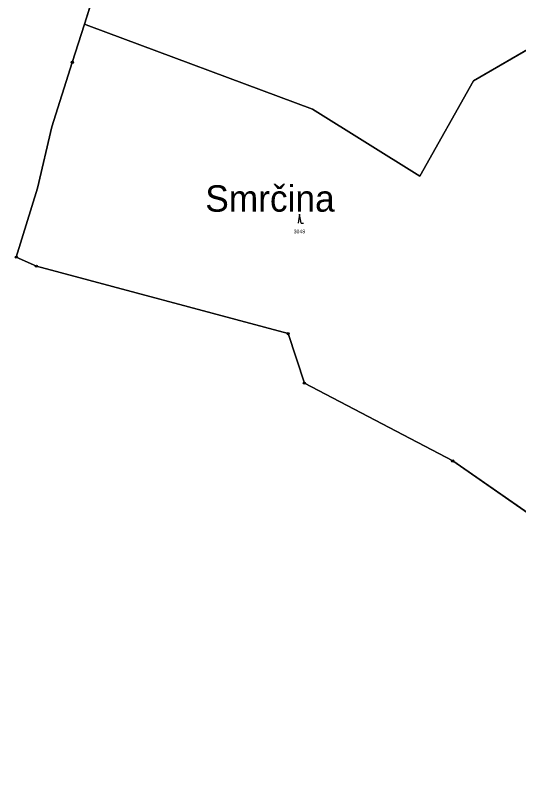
# Model space of a CAD drawing. Extents: x -689422 to -685210, y -987725 to -982160.
# Drawn here: x -688746.1 to -688517.1, y -986803.6 to -986459.2 of the extents above; entities that cross this region are included whole.
import ezdxf

# ---------------------------------------------------------------- set-up
doc = ezdxf.new("R2010")
doc.units = 0
for name, color, linetype in [('KN_Hranice obce', 7, 'Continuous'), ('KN_Hranice_katastrální území', 7, 'Continuous'), ('KN_Hranice_parcel', 7, 'Continuous'), ('KN_Parcelni cisla', 7, 'Continuous'), ('KN_Polygon parcely', 7, 'Continuous'), ('KN_Popisy_pomistni nazvy', 7, 'Continuous'), ('KN_POZEMKY_LESNI POZEMEK', 7, 'Continuous'), ('KN_POZEMKY_TTP', 7, 'Continuous'), ('KN_Značky bodu BP', 7, 'Continuous'), ('KN_Značky kultur', 7, 'Continuous')]:
    doc.layers.add(name, color=color, linetype=linetype)

msp = doc.modelspace()

# ---------------------------------------------------------------- linework, layer by layer
at = {"layer": 'KN_Hranice obce'}
msp.add_lwpolyline([(-688702.54, -986425.02), (-688714.66, -986463.31), (-688720.16, -986480.67), (-688729.49, -986509.98), (-688735.94, -986537.91), (-688745.64, -986569.21), (-688736.48, -986573.33), (-688622, -986603.98), (-688614.63, -986626.48), (-688547.16, -986661.81), (-688502.75, -986692.68), (-688511.14, -986710.83), (-688455.25, -986756.85), (-688406.43, -986788.29), (-688396.34, -986794.79), (-688378.96, -986803.58)], dxfattribs=at)
at = {"layer": 'KN_Hranice_katastrální území'}
msp.add_lwpolyline([(-688702.54, -986425.02), (-688714.66, -986463.31), (-688720.16, -986480.67), (-688729.49, -986509.98), (-688735.94, -986537.91), (-688745.64, -986569.21), (-688736.48, -986573.33), (-688622, -986603.98), (-688614.63, -986626.48), (-688547.16, -986661.81), (-688502.75, -986692.68), (-688511.14, -986710.83), (-688455.25, -986756.85), (-688406.43, -986788.29), (-688396.34, -986794.79), (-688378.96, -986803.58)], dxfattribs=at)
at = {"layer": 'KN_Hranice_parcel'}
for p, q in [((-688714.66, -986463.31), (-688702.54, -986425.02)), ((-688745.64, -986569.21), (-688736.48, -986573.33))]:
    msp.add_line(p, q, dxfattribs=at)
for points in [[(-688440.57, -986455.42), (-688464.06, -986454.46), (-688490.47, -986461.68), (-688537.78, -986489.13), (-688562.11, -986532.46), (-688610.93, -986501.88), (-688712.6, -986464.08), (-688714.66, -986463.31)], [(-688745.64, -986569.21), (-688735.94, -986537.91), (-688729.49, -986509.98), (-688720.16, -986480.67), (-688714.66, -986463.31)], [(-688736.48, -986573.33), (-688622, -986603.98), (-688614.63, -986626.48), (-688547.16, -986661.81), (-688502.75, -986692.68)]]:
    msp.add_lwpolyline(points, dxfattribs=at)
at = {"layer": 'KN_Polygon parcely'}
msp.add_lwpolyline([(-688462.76, -986403.5), (-688515.68, -986400.86), (-688548.75, -986389.63), (-688567.73, -986373.72), (-688579.19, -986344.94), (-688583.99, -986297.77), (-688586.55, -986293.85), (-688603.03, -986291.71), (-688615.78, -986427.72), (-688641.13, -986426.91), (-688699.18, -986415.43), (-688699.56, -986416.51), (-688702.54, -986425.02), (-688714.66, -986463.31), (-688712.6, -986464.08), (-688610.93, -986501.88), (-688562.11, -986532.46), (-688537.78, -986489.13), (-688490.47, -986461.68), (-688464.06, -986454.46), (-688440.57, -986455.42), (-688425.03, -986420.17), (-688434.24, -986408.86)], close=True, dxfattribs=at)
msp.add_lwpolyline([(-688490.47, -986461.68), (-688537.78, -986489.13), (-688562.11, -986532.46), (-688610.93, -986501.88), (-688712.6, -986464.08), (-688714.66, -986463.31), (-688720.16, -986480.67), (-688729.49, -986509.98), (-688735.94, -986537.91), (-688745.64, -986569.21), (-688736.48, -986573.33), (-688622, -986603.98), (-688614.63, -986626.48), (-688547.16, -986661.81), (-688502.75, -986692.68)], dxfattribs=at)
at = {"layer": 'KN_POZEMKY_LESNI POZEMEK'}
for p, q in [((-688720.16, -986480.67), (-688714.66, -986463.31)), ((-688714.66, -986463.31), (-688712.6, -986464.08)), ((-688712.6, -986464.08), (-688610.93, -986501.88)), ((-688537.78, -986489.13), (-688490.47, -986461.68)), ((-688729.49, -986509.98), (-688720.16, -986480.67)), ((-688562.11, -986532.46), (-688537.78, -986489.13)), ((-688610.93, -986501.88), (-688562.11, -986532.46)), ((-688735.94, -986537.91), (-688729.49, -986509.98)), ((-688745.64, -986569.21), (-688735.94, -986537.91)), ((-688736.48, -986573.33), (-688745.64, -986569.21)), ((-688622, -986603.98), (-688736.48, -986573.33)), ((-688614.63, -986626.48), (-688622, -986603.98)), ((-688547.16, -986661.81), (-688614.63, -986626.48)), ((-688502.75, -986692.68), (-688547.16, -986661.81))]:
    msp.add_line(p, q, dxfattribs=at)
at = {"layer": 'KN_POZEMKY_TTP'}
for p, q in [((-688714.66, -986463.31), (-688702.54, -986425.02)), ((-688712.6, -986464.08), (-688714.66, -986463.31)), ((-688610.93, -986501.88), (-688712.6, -986464.08)), ((-688490.47, -986461.68), (-688537.78, -986489.13)), ((-688537.78, -986489.13), (-688562.11, -986532.46)), ((-688562.11, -986532.46), (-688610.93, -986501.88))]:
    msp.add_line(p, q, dxfattribs=at)
at = {"layer": 'KN_Značky bodu BP'}
for centre, radius in [((-688720.16, -986480.67), 0.5), ((-688720.16, -986480.67), 0.0303), ((-688745.64, -986569.21), 0.5), ((-688745.64, -986569.21), 0.0303), ((-688736.48, -986573.33), 0.5), ((-688736.48, -986573.33), 0.0303), ((-688622, -986603.98), 0.5), ((-688622, -986603.98), 0.0303), ((-688614.63, -986626.48), 0.5), ((-688614.63, -986626.48), 0.0303), ((-688547.16, -986661.81), 0.5), ((-688547.16, -986661.81), 0.0303)]:
    msp.add_circle(centre, radius, dxfattribs=at)
at = {"layer": 'KN_Značky kultur'}
for p, q in [((-688616.76, -986549.69), (-688617.51, -986553.69)), ((-688616.01, -986553.69), (-688616.76, -986549.69)), ((-688616.01, -986553.69), (-688615.01, -986553.69))]:
    msp.add_line(p, q, dxfattribs=at)

# ---------------------------------------------------------------- texts
at = {"layer": 'KN_Parcelni cisla'}
msp.add_text('3048', height=1.7, dxfattribs=at).set_placement((-688619.49, -986558.38))
at = {"layer": 'KN_Popisy_pomistni nazvy'}
msp.add_text('Smrčina', height=12, dxfattribs=at).set_placement((-688659.68, -986548.54))

doc.saveas('drawing.dxf')
